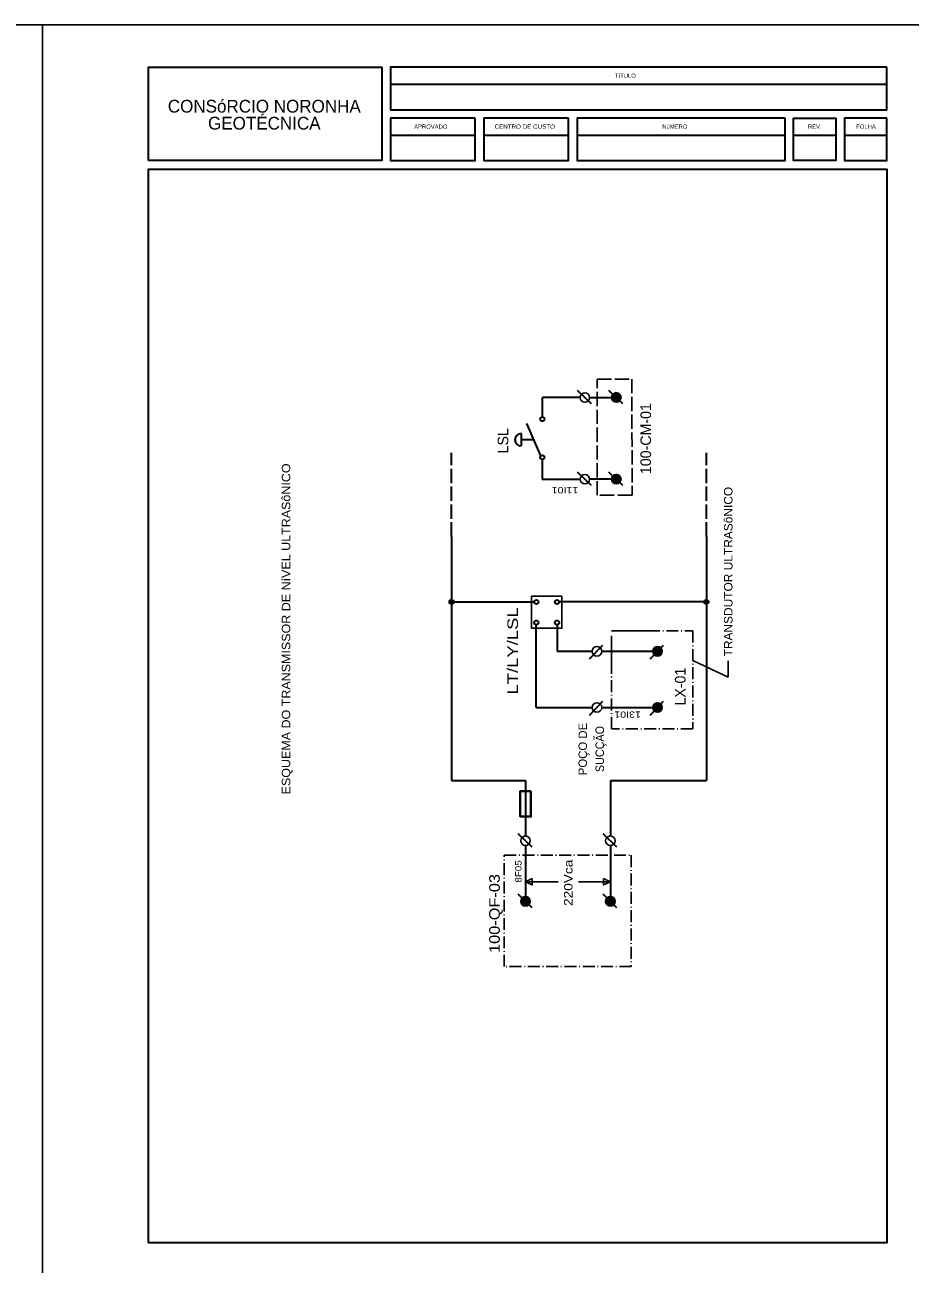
# Model space of a CAD drawing. Extents: x -4160 to -2690, y -474 to 714.
# Drawn here: x -3743.9 to -3535.3, y -171.5 to 120.5 of the extents above; entities that cross this region are included whole.
import ezdxf
from ezdxf.enums import TextEntityAlignment as Align

# ---------------------------------------------------------------- set-up
doc = ezdxf.new("R2010")
doc.units = 0
doc.header["$LTSCALE"] = 0.56
doc.linetypes.add('DOT_DASHED', pattern=[7.7, 5, -1.2, 0.3, -1.2])
doc.linetypes.add('LONG_DASHED', pattern=[7.5, 6, -1.5])
for name, color, linetype, lineweight in [('1', 7, 'Continuous', 25), ('2', 7, 'Continuous', 25), ('5', 7, 'Continuous', 35)]:
    doc.layers.add(name, color=color, linetype=linetype, lineweight=lineweight)

msp = doc.modelspace()

# ---------------------------------------------------------------- hatches: boundary and pattern name
at = {"layer": '2'}
for points in [[(-3604.5399, 31.5692, 1), (-3604.5399, 33.817, 1)], [(-3604.5399, 12.3138, 1), (-3604.5399, 14.5616, 1)], [(-3643.3543, -14.9867, 1), (-3643.3543, -16.0181, 1)], [(-3583.2847, -14.9867, 1), (-3583.2847, -16.0181, 1)], [(-3593.6867, -27.1255, 1), (-3595.9345, -27.1255, 1)], [(-3593.6867, -40.3584, 1), (-3595.9345, -40.3584, 1)], [(-3625.9187, -87.1581, 1), (-3625.9187, -84.9103, 1)], [(-3605.9187, -87.1581, 1), (-3605.9187, -84.9103, 1)]]:
    msp.add_hatch(color=256, dxfattribs=at).paths.add_polyline_path(points)

# ---------------------------------------------------------------- linework, layer by layer
at = {"layer": '1'}
msp.add_lwpolyline([(-3617.3284, -14.1695), (-3617.3284, -21.6818), (-3624.4885, -21.6818), (-3624.4885, -14.1695)], close=True, dxfattribs=at)
at = {"layer": '2', "lineweight": 35}
for p, q in [((-3621.9475, 28.0776), (-3621.9475, 32.7063)), ((-3613.0544, 32.7063), (-3621.9475, 32.7063)), ((-3613.7216, 34.4128), (-3610.4755, 31.2656)), ((-3610.8066, 32.7063), (-3605.6637, 32.7063)), ((-3606.331, 34.4324), (-3603.0849, 31.2852)), ((-3622.3011, 18.924), (-3625.6053, 26.5163)), ((-3626.9807, 24.1623), (-3626.9807, 21.2778)), ((-3623.9532, 22.7201), (-3626.9807, 22.7201)), ((-3621.9916, 18.0796), (-3621.9916, 13.4509)), ((-3613.7216, 15.1574), (-3610.4755, 12.0102)), ((-3606.331, 15.177), (-3603.0849, 12.0298)), ((-3621.9916, 13.4509), (-3613.0544, 13.4509)), ((-3605.6637, 13.4509), (-3610.8066, 13.4509)), ((-3643.3543, -0.0892), (-3643.3543, -57.5602)), ((-3583.2847, -0.0892), (-3583.2847, -57.5602)), ((-3643.3543, -15.5024), (-3623.8634, -15.5024)), ((-3583.2847, -15.5024), (-3617.9536, -15.5024)), ((-3623.3742, -40.3584), (-3623.3742, -20.8488)), ((-3618.4913, -20.8488), (-3618.4913, -27.1255)), ((-3610.8263, -28.9166), (-3607.6791, -25.6705)), ((-3596.5499, -28.9166), (-3593.4027, -25.6705)), ((-3618.4913, -27.1255), (-3610.2109, -27.1255)), ((-3607.9631, -27.1255), (-3595.9345, -27.1255)), ((-3623.3742, -40.3584), (-3610.2109, -40.3584)), ((-3610.8263, -42.1495), (-3607.6791, -38.9034)), ((-3607.9631, -40.3584), (-3595.9345, -40.3584)), ((-3596.5499, -42.1495), (-3593.4027, -38.9034)), ((-3643.3543, -57.5602), (-3625.9187, -57.5602)), ((-3625.9187, -57.5602), (-3625.9187, -68.1892)), ((-3605.9187, -57.5602), (-3605.9187, -70.6339)), ((-3605.9187, -57.5602), (-3583.2847, -57.5602)), ((-3625.9187, -65.289), (-3625.9187, -70.6339)), ((-3627.7098, -70.0185), (-3624.4637, -73.1657)), ((-3607.7098, -70.0185), (-3604.4637, -73.1657)), ((-3625.9187, -72.8817), (-3625.9187, -84.9103)), ((-3605.9187, -72.8817), (-3605.9187, -84.9103)), ((-3627.7098, -84.2949), (-3624.4637, -87.4421)), ((-3607.7098, -84.2949), (-3604.4637, -87.4421))]:
    msp.add_line(p, q, dxfattribs=at)
at = {"layer": '2', "linetype": 'LONG_DASHED', "lineweight": 35}
for p, q in [((-3643.3543, -0.0892), (-3643.3543, 19.6122)), ((-3583.2847, -0.0892), (-3583.2847, 19.6122))]:
    msp.add_line(p, q, dxfattribs=at)
at = {"layer": '2', "linetype": 'DOT_DASHED'}
msp.add_line((-3605.6551, -30.2449), (-3605.6551, -23.4778), dxfattribs=at)
at = {"layer": '2'}
for p, q in [((-3586.4959, -29.2828), (-3578.1417, -33.1815)), ((-3578.1417, -33.1815), (-3578.1417, -29.3642)), ((-3625.9187, -81.396), (-3618.1937, -81.396)), ((-3613.441, -81.396), (-3605.9187, -81.396))]:
    msp.add_line(p, q, dxfattribs=at)
at = {"layer": '2', "linetype": 'LONG_DASHED'}
msp.add_lwpolyline([(-3600.815, 9.6436), (-3609.0291, 9.6353), (-3609.0567, 37.0193), (-3600.8426, 37.0276)], close=True, dxfattribs=at)
at = {"layer": '2', "linetype": 'DOT_DASHED'}
msp.add_lwpolyline([(-3596.0853, -22.2694), (-3605.6551, -22.2694), (-3586.5156, -22.2694), (-3586.5156, -45.3584), (-3605.6551, -45.3584), (-3605.6551, -23.4778)], dxfattribs=at)
at = {"layer": '2', "lineweight": 40}
msp.add_lwpolyline([(-3624.659, -60.0684), (-3624.659, -66.0442), (-3627.1784, -66.0442), (-3627.1784, -60.0684)], close=True, dxfattribs=at)
at = {"layer": '2', "linetype": 'DOT_DASHED'}
msp.add_lwpolyline([(-3630.9187, -101.396), (-3630.9187, -75.1897), (-3600.9933, -75.1897), (-3600.9933, -101.396)], close=True, dxfattribs=at)
at = {"layer": '2'}
for points in [[(-3624.3277, -80.6402), (-3624.3277, -82.1519), (-3625.9187, -81.396)], [(-3607.5097, -80.6402), (-3607.5097, -82.1519), (-3605.9187, -81.396)]]:
    msp.add_lwpolyline(points, close=True, dxfattribs=at)
for centre in [(-3611.9305, 32.6735), (-3604.5399, 32.6931), (-3611.9305, 13.4181), (-3604.5399, 13.4377), (-3609.087, -27.1255), (-3594.8106, -27.1255), (-3609.087, -40.3584), (-3594.8106, -40.3584), (-3625.9187, -71.7578), (-3605.9187, -71.7578), (-3625.9187, -86.0342), (-3605.9187, -86.0342)]:
    msp.add_circle(centre, 1.1239, dxfattribs=at)
at = {"layer": '2', "lineweight": 35}
for centre, radius in [((-3621.9476, 27.5776), 0.5), ((-3621.9476, 18.5777), 0.5), ((-3643.3543, -15.5024), 0.5157), ((-3623.3635, -15.5024), 0.5), ((-3618.4806, -15.5024), 0.5), ((-3583.2847, -15.5024), 0.5157), ((-3623.3635, -20.3489), 0.5), ((-3618.4806, -20.3489), 0.5)]:
    msp.add_circle(centre, radius, dxfattribs=at)
msp.add_arc((-3626.9807, 22.7201), 1.4423, 90, 270, dxfattribs=at)
at = {"layer": '5', "lineweight": 25}
for p, q in [((-3739.7642, -176.52), (-3739.7642, 120.48)), ((-3739.7642, 120.48), (-3529.7642, 120.48))]:
    msp.add_line(p, q, dxfattribs=at)
at = {"layer": '5'}
for p, q in [((-3657.7642, 106.48), (-3540.7642, 106.48)), ((-3657.7642, 94.48), (-3637.7642, 94.48)), ((-3635.7642, 94.48), (-3615.7642, 94.48)), ((-3613.7642, 94.48), (-3564.7642, 94.48)), ((-3562.7642, 94.48), (-3552.7642, 94.48)), ((-3550.7642, 94.48), (-3540.7642, 94.48))]:
    msp.add_line(p, q, dxfattribs=at)
at = {"layer": '5', "lineweight": 25}
msp.add_lwpolyline([(-3739.7642, -176.52), (-3949.7642, -176.52), (-3949.7642, 120.48), (-3739.7642, 120.48)], close=True, dxfattribs=at)
at = {"layer": '5'}
for points in [[(-3714.7642, 88.48), (-3714.7642, 110.48), (-3659.7642, 110.48), (-3659.7642, 88.48)], [(-3540.7642, 110.48), (-3657.7642, 110.48), (-3657.7642, 100.48), (-3540.7642, 100.48)], [(-3637.7642, 98.48), (-3657.7642, 98.48), (-3657.7642, 88.48), (-3637.7642, 88.48)], [(-3615.7642, 98.48), (-3635.7642, 98.48), (-3635.7642, 88.48), (-3615.7642, 88.48)], [(-3564.7642, 98.48), (-3613.7642, 98.48), (-3613.7642, 88.48), (-3564.7642, 88.48)], [(-3562.7642, 98.48), (-3552.7642, 98.48), (-3552.7642, 88.48), (-3562.7642, 88.48)], [(-3540.7642, 98.48), (-3550.7642, 98.48), (-3550.7642, 88.48), (-3540.7642, 88.48)], [(-3714.7642, -166.52), (-3714.7642, 86.48), (-3540.7642, 86.48), (-3540.7642, -166.52)]]:
    msp.add_lwpolyline(points, close=True, dxfattribs=at)

# ---------------------------------------------------------------- texts
at = {"layer": '2'}
for s, height, p in [('100-CM-01', 2.5, (-3596.3424, 22.9836)), ('LSL', 2.5, (-3629.9713, 22.4679)), ('LX-01', 2.5, (-3588.2093, -35.4507)), ('POÇO DE', 2, (-3611.4272, -50.148))]:
    msp.add_text(s, height=height, rotation=90, dxfattribs=at).set_placement(p, align=Align.CENTER)
for s, height, rotation, width, p in [('ESQUEMA DO TRANSMISSOR DE NíVEL ULTRASôNICO', 2, 90, 1.1, (-3681.3509, -21.8497)), ('11I01', 1.5, 180, 1.25, (-3616.614, 11.5792)), ('TRANSDUTOR ULTRASôNICO', 2, 90, 1.05, (-3577.1469, -8.3492)), ('LT/LY/LSL', 2.5, 90, 1.3, (-3627.697, -27.037)), ('13I01', 1.5, 180, 1.25, (-3601.8533, -41.303)), ('SUCÇÃO', 2, 90, 0.95, (-3607.4272, -50.148)), ('8F05', 1.5, 90, 1.15, (-3626.8633, -78.9915)), ('220Vca', 2, 90, 1.2, (-3614.8464, -81.6685)), ('100-QF-03', 2.5, 90, 1.15, (-3631.9841, -88.8963))]:
    msp.add_text(s, height=height, rotation=rotation, dxfattribs=dict(at, width=width)).set_placement(p, align=Align.CENTER)
at = {"layer": '5'}
for s, height, p in [('TíTULO', 1, (-3602.3847, 107.991)), ('CONSóRCIO NORONHA', 3, (-3687.4749, 99.7961)), ('GEOTÉCNICA', 3, (-3687.475, 95.7961)), ('APROVADO', 1, (-3648.2387, 95.9973)), ('REV.', 1, (-3557.7444, 95.9923)), ('FOLHA', 1, (-3545.681, 95.9923))]:
    msp.add_text(s, height=height, dxfattribs=at).set_placement(p, align=Align.CENTER)
for s, width, p in [('CENTRO DE CUSTO', 1.1, (-3626.0934, 95.9973)), ('NúMERO', 0.95, (-3590.7228, 95.9923))]:
    msp.add_text(s, height=1, dxfattribs=dict(at, width=width)).set_placement(p, align=Align.CENTER)

doc.saveas('drawing.dxf')
